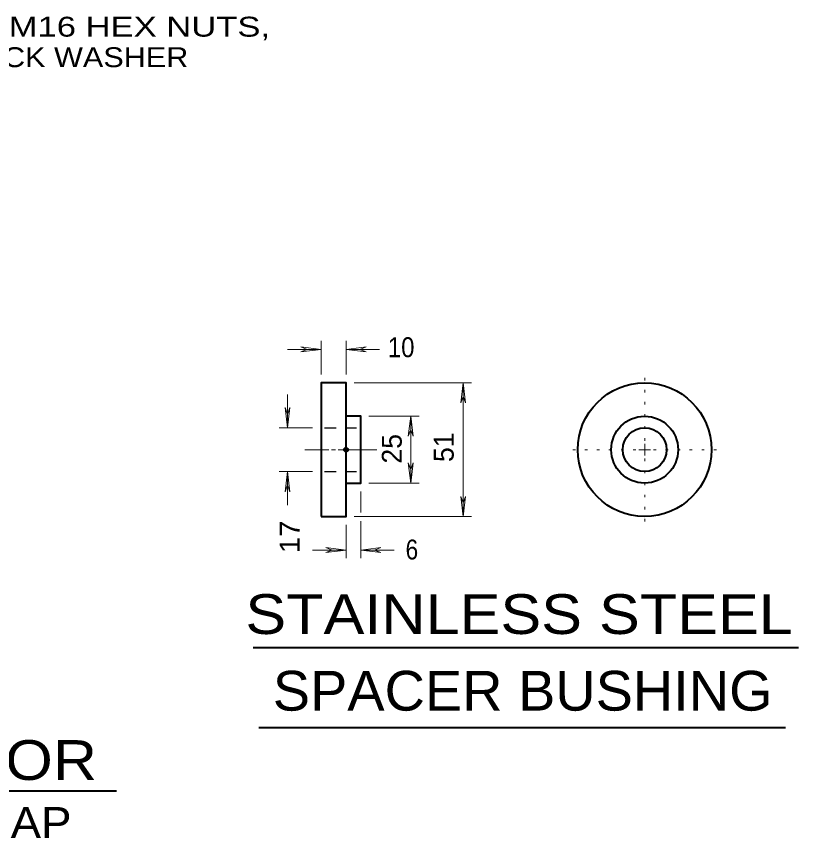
# Model space of a CAD drawing. Extents: x 312583 to 312854, y 144419 to 144597.
# Drawn here: x 312726.34 to 312756.22, y 144485.73 to 144517.14 of the extents above; entities that cross this region are included whole.
import ezdxf
from ezdxf.enums import TextEntityAlignment as Align

# ---------------------------------------------------------------- set-up
doc = ezdxf.new("R2010")
doc.units = 0
doc.header["$LTSCALE"] = 0.3
doc.header["$PDMODE"] = 32
doc.header["$PDSIZE"] = 0.15
doc.linetypes.add('DOTTED', pattern=[1.5, 0.3, -1.2])
doc.linetypes.add('SHORT_DASHED', pattern=[2.7, 1.5, -1.2])
doc.layers.add('1', color=7, linetype='Continuous', lineweight=40)

msp = doc.modelspace()

# ---------------------------------------------------------------- linework, layer by layer
at = {"layer": '1', "lineweight": 13}
for p, q in [((312737.9786, 144503.4606), (312737.9786, 144504.741)), ((312738.937, 144503.4606), (312738.937, 144504.741)), ((312737.9786, 144504.419), (312736.6983, 144504.419)), ((312737.2043, 144504.5186), (312737.4496, 144504.419)), ((312737.9786, 144504.419), (312737.2043, 144504.5186)), ((312737.2043, 144504.327), (312737.4496, 144504.419)), ((312737.9786, 144504.419), (312737.2043, 144504.327)), ((312738.937, 144504.419), (312739.7036, 144504.5186)), ((312740.2096, 144504.419), (312738.937, 144504.419)), ((312738.937, 144504.419), (312739.7036, 144504.327)), ((312739.7036, 144504.5186), (312739.4583, 144504.419)), ((312739.7036, 144504.327), (312739.4583, 144504.419)), ((312739.2513, 144503.1463), (312743.7286, 144503.1463)), ((312743.4066, 144503.1463), (312743.3146, 144502.372)), ((312743.4066, 144498.0326), (312743.4066, 144503.1463)), ((312743.4066, 144503.1463), (312743.4986, 144502.372)), ((312736.6983, 144501.429), (312736.6983, 144502.7016)), ((312743.3146, 144502.372), (312743.4066, 144502.6173)), ((312743.4986, 144502.372), (312743.4066, 144502.6173)), ((312736.6063, 144502.1956), (312736.6983, 144501.9503)), ((312736.6983, 144501.429), (312736.6063, 144502.1956)), ((312736.7903, 144502.1956), (312736.6983, 144501.9503)), ((312736.6983, 144501.429), (312736.7903, 144502.1956)), ((312739.811, 144501.866), (312741.7276, 144501.866)), ((312741.4133, 144501.866), (312741.3136, 144501.0993)), ((312741.4133, 144499.313), (312741.4133, 144501.866)), ((312741.4133, 144501.866), (312741.5053, 144501.0993)), ((312737.6566, 144501.429), (312736.3763, 144501.429)), ((312741.3136, 144501.0993), (312741.4133, 144501.3446)), ((312741.5053, 144501.0993), (312741.4133, 144501.3446)), ((312738.2776, 144500.5856), (312737.3576, 144500.5856)), ((312738.5306, 144500.5856), (312738.3773, 144500.5856)), ((312738.6303, 144500.5856), (312740.1176, 144500.5856)), ((312750.345, 144500.5856), (312750.115, 144500.5856)), ((312750.345, 144500.5856), (312750.345, 144500.8156)), ((312750.345, 144500.5856), (312750.345, 144500.3633)), ((312750.345, 144500.5856), (312750.5673, 144500.5856)), ((312741.3136, 144500.0796), (312741.4133, 144499.8343)), ((312741.4133, 144499.313), (312741.3136, 144500.0796)), ((312741.5053, 144500.0796), (312741.4133, 144499.8343)), ((312741.4133, 144499.313), (312741.5053, 144500.0796)), ((312737.6566, 144499.75), (312736.3763, 144499.75)), ((312736.6983, 144499.75), (312736.6063, 144498.9833)), ((312736.6983, 144498.4696), (312736.6983, 144499.75)), ((312736.6983, 144499.75), (312736.7903, 144498.9833)), ((312739.811, 144499.313), (312741.7276, 144499.313)), ((312736.6063, 144498.9833), (312736.6983, 144499.2286)), ((312736.7903, 144498.9833), (312736.6983, 144499.2286)), ((312739.4966, 144498.991), (312739.4966, 144498.1936)), ((312743.3146, 144498.7993), (312743.4066, 144498.554)), ((312743.4066, 144498.0326), (312743.3146, 144498.7993)), ((312743.4986, 144498.7993), (312743.4066, 144498.554)), ((312743.4066, 144498.0326), (312743.4986, 144498.7993)), ((312739.2513, 144498.0326), (312743.7286, 144498.0326)), ((312739.4966, 144497.8563), (312739.4966, 144496.438)), ((312738.937, 144497.7106), (312738.937, 144496.438)), ((312738.1626, 144496.852), (312738.408, 144496.7523)), ((312738.937, 144496.7523), (312738.1626, 144496.852)), ((312739.4966, 144496.7523), (312740.2633, 144496.852)), ((312740.2633, 144496.852), (312740.018, 144496.7523)), ((312738.937, 144496.7523), (312737.6566, 144496.7523)), ((312738.1626, 144496.6603), (312738.408, 144496.7523)), ((312738.937, 144496.7523), (312738.1626, 144496.6603)), ((312740.7693, 144496.7523), (312739.4966, 144496.7523)), ((312739.4966, 144496.7523), (312740.2633, 144496.6603)), ((312740.2633, 144496.6603), (312740.018, 144496.7523))]:
    msp.add_line(p, q, dxfattribs=at)
at = {"layer": '1', "linetype": 'DOTTED', "lineweight": 13}
for p, q in [((312750.345, 144500.9306), (312750.345, 144503.5066)), ((312750, 144500.5856), (312747.4316, 144500.5856)), ((312750.6823, 144500.5856), (312753.2813, 144500.5856)), ((312750.345, 144500.2483), (312750.345, 144497.7413))]:
    msp.add_line(p, q, dxfattribs=at)
at = {"layer": '1', "linetype": 'SHORT_DASHED', "lineweight": 25}
for p, q in [((312738.109, 144501.429), (312739.3356, 144501.429)), ((312738.109, 144499.75), (312739.3356, 144499.75))]:
    msp.add_line(p, q, dxfattribs=at)
at = {"layer": '1'}
for p, q in [((312735.3867, 144493.0283), (312756.2226, 144493.0283)), ((312735.5993, 144489.9785), (312755.7265, 144489.9785)), ((312701.4873, 144487.5487), (312730.1686, 144487.5487))]:
    msp.add_line(p, q, dxfattribs=at)
msp.add_lwpolyline([(312737.9786, 144498.0326), (312738.937, 144498.0326), (312738.937, 144503.1463), (312737.9786, 144503.1463)], close=True, dxfattribs=at)
msp.add_lwpolyline([(312738.937, 144499.313), (312739.4966, 144499.313), (312739.4966, 144501.866), (312738.937, 144501.866)], dxfattribs=at)
for radius in [2.5556, 1.2778, 0.8385]:
    msp.add_circle((312750.3424, 144500.5882), radius, dxfattribs=at)
msp.add_point((312738.937, 144500.5856), dxfattribs=at)

# ---------------------------------------------------------------- texts
for s, width, p in [('THD LG. 2 X DIA. + 6 MM - 0, 2 M16 HEX NUTS,', 1.3, (312706.9963, 144516.3693)), ('2 M16 FLAT WASHERS, & ONE LOCK WASHER', 1.15, (312706.9963, 144515.203)), ('10', 0.9, (312740.5328, 144504.1225)), ('6', 0.85, (312741.2105, 144496.3936))]:
    msp.add_text(s, height=0.76, dxfattribs=dict(at, width=width)).set_placement(p)
for s, p in [('51 ', (312743.0468, 144500.1162)), ('25', (312741.0632, 144500.0559))]:
    msp.add_text(s, height=0.76, rotation=90, dxfattribs=at).set_placement(p)
at = {"layer": '1', "width": 1.1}
msp.add_text(' 17', height=0.76, rotation=90, dxfattribs=at).set_placement((312737.1607, 144496.3249))
at = {"layer": '1'}
for s, height, width, p in [('STAINLESS STEEL', 1.52, 1.15, (312745.5466, 144493.5466)), ('SPACER BUSHING', 1.52, 1.05, (312745.6835, 144490.6179)), ('STN. STL. BUSHING FOR', 1.52, 1.15, (312715.525, 144487.9696)), ('ALTERNATE MOUNTING STRAP', 1.186, 1.1, (312715.1684, 144485.7471))]:
    msp.add_text(s, height=height, dxfattribs=dict(at, width=width)).set_placement(p, align=Align.CENTER)

doc.saveas('drawing.dxf')
